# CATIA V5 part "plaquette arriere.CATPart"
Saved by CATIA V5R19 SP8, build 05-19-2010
Part number: plaquette arriere
Bounding box of the stored display mesh (mm): x 0 to 4.5, y 0 to 21.5, z 0 to 14
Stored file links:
  C:\Users\Arthur\Desktop\Catia parts\GLOCK\Ensemble culasse\plaquette arriere.CATPart
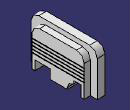
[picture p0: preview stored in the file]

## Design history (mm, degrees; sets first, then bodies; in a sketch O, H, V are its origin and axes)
Body1 (main body)
  Sketch1 on yz-plane, origin (0, 0, 0), H (0, 1, 0), V (0, 0, 1)
    line L1 (0, 0) -> (21.5, 0)
    line L2 (21.5, 0) -> (21.5, 11.5)
    line L3 (19, 14) -> (2.5, 14)
    line L4 (0, 11.5) -> (0, 0)
    arc A1 centre (2.5, 11.5) radius 2.5 from (0, 11.5) to (2.5, 14) cw
    arc A2 centre (19, 11.5) radius 2.5 from (19, 14) to (21.5, 11.5) cw
    length L1 = 21.5
    radius A1 = 2.5
    radius A2 = 2.5
    distance L3 L1 = 14
    horizontal: L1 H, L3 H
    vertical: L2 V, L4 V
    tangency: A1 L4, A1 L3, A2 L3, A2 L2
  Pad1: profile Sketch1, direction (1, 0, 0), length 2.5
  Sketch2 on end face of Pad1, origin (2.5, 0, 0), H (0, 1, 0), V (0, 0, 1)
    line L1 (2.25, 0) -> (19.25, 0)
    line L2 (19.25, 0) -> (19.25, 10)
    line L3 (16.75, 12.5) -> (4.75, 12.5)
    line L4 (2.25, 10) -> (2.25, 0)
    reference projected line E1 (0, 0) -> (21.5, 0) from edge [face of Pad1 from Sketch1.L1 | end face of Pad1]
    arc A1 centre (4.75, 10) radius 2.5 from (4.75, 12.5) to (2.25, 10) ccw
    arc A2 centre (16.75, 10) radius 2.5 from (16.75, 12.5) to (19.25, 10) cw
    reference projected line E2 (19, 14) -> (2.5, 14) from edge [face of Pad1 from Sketch1.L3 | end face of Pad1]
    reference projected line E3 (0, 11.5) -> (0, 0) from edge [face of Pad1 from Sketch1.L4 | end face of Pad1]
    reference projected line E4 (21.5, 0) -> (21.5, 11.5) from edge [face of Pad1 from Sketch1.L2 | end face of Pad1]
    radius A1 = 2.5
    radius A2 = 2.5
    distance L3 E2 = 1.5
    distance L4 E3 = 2.25
    distance L2 E4 = 2.25
    horizontal: L1 H, L3 H
    vertical: L2 V, L4 V
    coincidence: L1 E1
    tangency: A1 L3, A1 L4, A2 L3, A2 L2
  Pad2: profile Sketch2, direction (1, 0, 0), length 2
  Sketch3 on end face of Pad2, origin (4.5, 0, 0), H (0, 1, 0), V (0, 0, 1)
    line L1 (3.25, 0) -> (8.25, 0)
    line L2 (8.25, 0) -> (8.25, 3)
    line L3 (8.25, 3) -> (3.25, 3)
    line L4 (3.25, 3) -> (3.25, 0)
    reference projected line E1 (2.25, 0) -> (19.25, 0) from edge [face of Pad2 from Sketch2.L1 | end face of Pad2]
    reference projected line E2 (2.25, 10) -> (2.25, 0) from edge [face of Pad2 from Sketch2.L4 | end face of Pad2]
    line L5 (18.25, 0) -> (13.75, 0)
    line L6 (18.25, 3.5) -> (18.25, 0)
    reference projected line E3 (2.25, 0) -> (19.25, 0) from edge [face of Pad2 from Sketch2.L1 | end face of Pad2]
    reference projected line E4 (19.25, 0) -> (19.25, 10) from edge [face of Pad2 from Sketch2.L2 | end face of Pad2]
    line L7 (18.25, 3.5) -> (15.75, 3.5)
    line L8 (15.75, 3.5) -> (15.75, 2.5)
    point P10 (13.75, 0)
    line L9 (13.75, 0) -> (13.75, 0.5)
    point P11 (13.75, 2.5)
    line L10 (15.75, 2.5) -> (15.75, 2.5)
    point P12 (13.75, 2.5)
    arc A1 centre (15.75, 0.5) radius 2 from (13.75, 0.5) to (15.75, 2.5) cw
    point P14 (15.75, 2.5)
    distance L4 E2 = 1
    distance L3 L1 = 3
    length L3 = 5
    distance L6 E4 = 1
    length L5 = 4.5
    distance L7 L5 = 3.5
    length L7 = 2.5
    length L8 = 1
    horizontal: L1 H, L3 H, L5 H, L7 H, L10 H
    vertical: L2 V, L4 V, L6 V, L8 V, L9 V
    coincidence: L1 E1, L5 E3, P12 P11, L9 P11, L10 P12, P14 L8
    tangency: A1 L9, A1 L10
  Pocket1: profile Sketch3, direction (-1, 0, 0), up to start face of Pad1
  Sketch4 on end face of Pad2, origin (4.5, 0, 0), H (0, 1, 0), V (0, 0, 1)
    line L1 (2.25, 4.7) -> (19.25, 4.7)
    line L2 (19.25, 4.7) -> (19.25, 4.5)
    line L3 (19.25, 4.5) -> (2.25, 4.5)
    line L4 (2.25, 4.5) -> (2.25, 4.7)
    reference projected line E1 (19.25, 0) -> (19.25, 10) from edge [face of Pad2 from Sketch2.L2 | end face of Pad2]
    reference projected line E2 (2.25, 10) -> (2.25, 0) from edge [face of Pad2 from Sketch2.L4 | end face of Pad2]
    reference projected line E3 (18.25, 3.5) -> (15.75, 3.5) from edge [end face of Pad2 | face of Pocket1 from Sketch3.L7]
    length L2 = 0.2
    distance E3 L3 = 1
    horizontal: L1 H, L3 H
    vertical: L2 V, L4 V
    coincidence: L2 E1, L4 E2
  Pocket2: profile Sketch4, direction (-1, 0, 0), length 0.1
  RectPattern1: of Pocket2, direction 1 instances 1, spacing 20, along end face of Pad2, direction 2 instances 5, spacing 1, along end face of Pad2
  Sketch5 on start face of Pad1, origin (0, 0, 0), H (0, -1, 0), V (0, 0, 1)
    axis line L1 (-10.75, 24.4053) -> (-10.75, -8.4053)
    reference projected line E1 (0, 11.5) -> (0, 0) from edge [start face of Pad1 | face of Pad1 from Sketch1.L4]
    reference projected line E2 (-21.5, 0) -> (-21.5, 11.5) from edge [start face of Pad1 | face of Pad1 from Sketch1.L2]
    circle A1 centre (-10.75, 8) radius 4
    point P3 (-10.75, 8)
    radius A1 = 4
    distance P3 H = 8
    vertical: L1 V
    symmetry: E1 E2 L1
    midpoint: P3 L1
  Pocket3: profile Sketch5, direction (1, 0, 0), length 1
